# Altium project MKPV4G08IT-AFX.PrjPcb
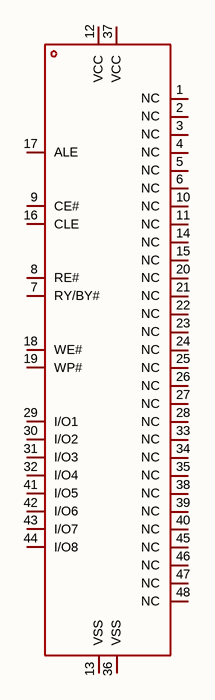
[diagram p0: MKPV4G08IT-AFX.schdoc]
1 sheet, 1 parts. Net scope: global (net labels, ports and power ports of the same name join across sheets).

## Sheet MKPV4G08IT-AFX.schdoc
size 127 x 101 mm

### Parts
U?  mkpv4g08it-afx  [TSOP-48_L18.4-W12.0-P0.50-LS20.0-TL]  (value not drawn)

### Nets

Not connected (* = marked no-connect by the designer): U? 1(NC) 2(NC) 3(NC) 4(NC) 5(NC) 6(NC) 7(RY/BY#) 8(RE#) 9(CE#) 10(NC) 11(NC) 12(VCC) 13(VSS) 14(NC) 15(NC) 16(CLE) 17(ALE) 18(WE#) 19(WP#) 20(NC) 21(NC) 22(NC) 23(NC) 24(NC) 25(NC) 26(NC) 27(NC) 28(NC) 29(I/O1) 30(I/O2) 31(I/O3) 32(I/O4) 33(NC) 34(NC) 35(NC) 36(VSS) 37(VCC) 38(NC) 39(NC) 40(NC) 41(I/O5) 42(I/O6) 43(I/O7) 44(I/O8) 45(NC) 46(NC) 47(NC) 48(NC)

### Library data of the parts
U? = mkpv4g08it-afx: 存储容量:4Gbit;时钟频率(fc):-;工作电压:2.7V~3.6V;; Manufacturer: MK(米客方德); AddInBom: yes; ModelId: 8ca44b2e5217496aa0ffcb8e0bdb3182; ModelTransform: 787.4,472.44,0,0,0,0,0,0,0; Memory Size: 4Gbit; Write Cycle Time(tWC): 25ns; Page Program time (TPP): 300us; Block Erase Time(tBE): 2.5ms; Standby Supply Current: 50uA; ECC: 有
